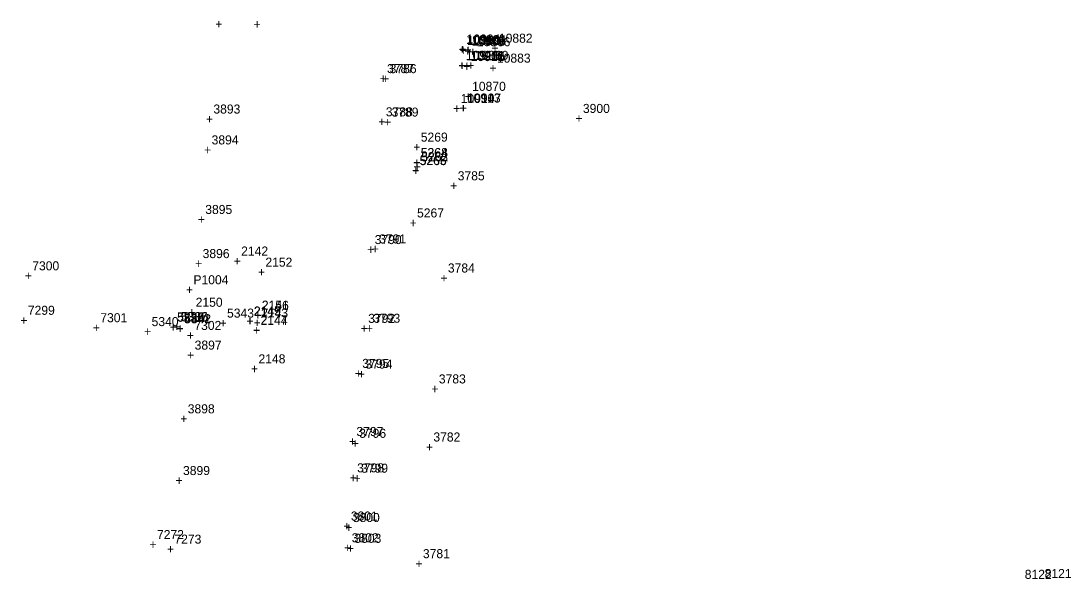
# Model space of a CAD drawing. Extents: x 1136220 to 1137808, y 528804 to 531215.
# Drawn here: x 1137338.4 to 1137628.2, y 530067.9 to 530222 of the extents above; entities that cross this region are included whole.
import ezdxf

# ---------------------------------------------------------------- set-up
doc = ezdxf.new("R2010")
doc.units = 0
for name, color, linetype in [('S_Buildings_SillElevation', 7, 'Continuous'), ('S_Curb_Type_1', 7, 'Continuous'), ('S_Drainage_CB', 7, 'Continuous'), ('S_Drainage_Culvert_Top', 7, 'Continuous'), ('S_Drainage_Invert', 7, 'Continuous'), ('S_Drainage_Sump', 7, 'Continuous'), ('S_Fencing_Gate', 7, 'Continuous'), ('S_Fencing_Picket', 7, 'Continuous'), ('S_Ground_Elevation', 7, 'Continuous'), ('S_Ground_SpotElevation', 7, 'Continuous'), ('S_Property_ConcPad', 7, 'Continuous'), ('S_Property_IronPipeFound', 7, 'Continuous'), ('S_Roadway_Drive_Gravel', 7, 'Continuous'), ('S_Roadway_Edge_Pavement', 7, 'Continuous'), ('S_Roadway_Sidewalks', 7, 'Continuous'), ('S_Utilities_UG_Sanitary_MH', 7, 'Continuous'), ('S_Utilities_UG_Water_Line', 7, 'Continuous')]:
    doc.layers.add(name, color=color, linetype=linetype)

msp = doc.modelspace()

# ---------------------------------------------------------------- texts
at = {"layer": 'S_Buildings_SillElevation'}
for s, p in [('+', (1137392.01, 530219.93)), ('3893', (1137391.47, 530196.46)), ('3900', (1137493.47, 530196.63)), ('+', (1137389.41, 530193.71)), ('+', (1137491.41, 530193.88)), ('3894', (1137390.98, 530187.94)), ('+', (1137388.92, 530185.19)), ('3785', (1137458.92, 530178.03)), ('+', (1137456.85, 530175.28)), ('3895', (1137389.23, 530168.73)), ('+', (1137387.17, 530165.98)), ('3896', (1137388.5, 530156.55)), ('+', (1137386.44, 530153.8)), ('3784', (1137456.2, 530152.57)), ('+', (1137454.14, 530149.82)), ('3897', (1137386.3, 530131.27)), ('+', (1137384.24, 530128.52)), ('3783', (1137453.71, 530121.94)), ('+', (1137451.65, 530119.19)), ('3898', (1137384.39, 530113.68)), ('+', (1137382.33, 530110.93)), ('3782', (1137452.2, 530105.9)), ('+', (1137450.14, 530103.15)), ('3899', (1137383.09, 530096.64)), ('+', (1137381.03, 530093.89)), ('3781', (1137449.31, 530073.68)), ('+', (1137447.25, 530070.93))]:
    msp.add_text(s, height=2.5, dxfattribs=at).set_placement(p)
at = {"layer": 'S_Curb_Type_1'}
for s, p in [('10909', (1137461.54, 530215.39)), ('10908', (1137462.78, 530215.19)), ('+', (1137459.48, 530212.64)), ('+', (1137460.72, 530212.44)), ('10910', (1137461.16, 530211.29)), ('10911', (1137462.57, 530211.28)), ('+', (1137459.09, 530208.54)), ('+', (1137460.51, 530208.53))]:
    msp.add_text(s, height=2.5, dxfattribs=at).set_placement(p)
at = {"layer": 'S_Drainage_CB'}
for s, p in [('+', (1137402.56, 530219.9)), ('5262', (1137448.87, 530183.26)), ('+', (1137446.81, 530180.51)), ('5336', (1137382.52, 530139.15)), ('+', (1137380.46, 530136.4))]:
    msp.add_text(s, height=2.5, dxfattribs=at).set_placement(p)
at = {"layer": 'S_Drainage_Culvert_Top'}
for s, p in [('5269', (1137448.72, 530188.71)), ('+', (1137446.66, 530185.96)), ('5268', (1137448.75, 530184.46)), ('5266', (1137448.45, 530182.22)), ('+', (1137446.39, 530179.47)), ('+', (1137446.69, 530181.71)), ('5267', (1137447.69, 530167.78)), ('+', (1137445.63, 530165.03)), ('2152', (1137405.83, 530154.18)), ('+', (1137403.77, 530151.43)), ('2150', (1137386.58, 530143.11)), ('2151', (1137404.84, 530142.31)), ('5339', (1137381.48, 530138.97)), ('5342', (1137383.39, 530138.53)), ('+', (1137384.52, 530140.36)), ('5343', (1137395.24, 530140.11)), ('2149', (1137402.69, 530140.65)), ('+', (1137402.78, 530139.56)), ('2147', (1137404.5, 530138.21)), ('5340', (1137374.42, 530137.77)), ('+', (1137379.42, 530136.22)), ('+', (1137381.33, 530135.78)), ('+', (1137393.18, 530137.36)), ('+', (1137400.63, 530137.9)), ('+', (1137372.36, 530135.02)), ('+', (1137402.44, 530135.46)), ('2148', (1137403.92, 530127.48)), ('+', (1137401.86, 530124.73))]:
    msp.add_text(s, height=2.5, dxfattribs=at).set_placement(p)
at = {"layer": 'S_Drainage_Invert'}
for s, p in [('5264', (1137448.68, 530184.43)), ('5265', (1137448.39, 530182.27)), ('+', (1137446.33, 530179.52)), ('+', (1137446.62, 530181.68)), ('2146', (1137404.86, 530142.27)), ('5338', (1137381.45, 530139.07)), ('5341', (1137383.38, 530138.62)), ('2145', (1137402.62, 530140.69)), ('+', (1137402.8, 530139.52)), ('2144', (1137404.5, 530138.12)), ('+', (1137379.39, 530136.32)), ('+', (1137381.32, 530135.87)), ('+', (1137400.56, 530137.94)), ('+', (1137402.44, 530135.37))]:
    msp.add_text(s, height=2.5, dxfattribs=at).set_placement(p)
at = {"layer": 'S_Drainage_Sump'}
for s, p in [('5263', (1137448.79, 530183.3)), ('+', (1137446.73, 530180.55)), ('5337', (1137382.42, 530139.09)), ('+', (1137380.36, 530136.34))]:
    msp.add_text(s, height=2.5, dxfattribs=at).set_placement(p)
at = {"layer": 'S_Fencing_Gate'}
for s, p in [('10906', (1137462.56, 530211.16)), ('+', (1137460.5, 530208.41))]:
    msp.add_text(s, height=2.5, dxfattribs=at).set_placement(p)
at = {"layer": 'S_Fencing_Picket'}
for s, p in [('10905', (1137462.86, 530215.59)), ('+', (1137460.8, 530212.84)), ('10907', (1137461.6, 530199.5)), ('+', (1137459.54, 530196.75))]:
    msp.add_text(s, height=2.5, dxfattribs=at).set_placement(p)
at = {"layer": 'S_Ground_Elevation'}
for s, p in [('10904', (1137461.39, 530215.82)), ('10903', (1137462.8, 530215.52)), ('+', (1137459.33, 530213.07)), ('+', (1137460.74, 530212.77)), ('10912', (1137462.51, 530210.96)), ('+', (1137460.45, 530208.21)), ('10913', (1137461.45, 530199.51)), ('+', (1137459.39, 530196.76)), ('8122', (1137615.44, 530067.97)), ('8121', (1137620.93, 530068.2))]:
    msp.add_text(s, height=2.5, dxfattribs=at).set_placement(p)
at = {"layer": 'S_Ground_SpotElevation'}
for s, p in [('10882', (1137470.28, 530216.03)), ('+', (1137468.22, 530213.28)), ('10883', (1137469.74, 530210.52)), ('+', (1137467.67, 530207.77))]:
    msp.add_text(s, height=2.5, dxfattribs=at).set_placement(p)
at = {"layer": 'S_Property_ConcPad'}
for s, p in [('10866', (1137464.16, 530215.05)), ('+', (1137462.1, 530212.3)), ('10869', (1137463.63, 530211.28)), ('+', (1137461.57, 530208.53)), ('10870', (1137462.89, 530202.74)), ('+', (1137460.83, 530199.99))]:
    msp.add_text(s, height=2.5, dxfattribs=at).set_placement(p)
at = {"layer": 'S_Property_IronPipeFound'}
for s, p in [('P1004', (1137385.96, 530149.32)), ('+', (1137383.9, 530146.57))]:
    msp.add_text(s, height=2.5, dxfattribs=at).set_placement(p)
at = {"layer": 'S_Roadway_Drive_Gravel'}
for s, p in [('7272', (1137375.9, 530078.96)), ('7273', (1137380.72, 530077.69)), ('+', (1137373.84, 530076.21)), ('+', (1137378.65, 530074.94))]:
    msp.add_text(s, height=2.5, dxfattribs=at).set_placement(p)
at = {"layer": 'S_Roadway_Edge_Pavement'}
for s, p in [('7300', (1137341.47, 530153.17)), ('+', (1137339.41, 530150.42)), ('7299', (1137340.26, 530140.89)), ('7301', (1137360.26, 530138.84)), ('+', (1137338.2, 530138.14)), ('+', (1137358.2, 530136.09)), ('7302', (1137386.22, 530136.7)), ('+', (1137384.16, 530133.95))]:
    msp.add_text(s, height=2.5, dxfattribs=at).set_placement(p)
at = {"layer": 'S_Roadway_Sidewalks'}
for s, p in [('10916', (1137461.23, 530215.67)), ('+', (1137459.17, 530212.92)), ('10915', (1137461.21, 530211.19)), ('+', (1137459.15, 530208.44)), ('10914', (1137459.74, 530199.37)), ('+', (1137457.68, 530196.62))]:
    msp.add_text(s, height=2.5, dxfattribs=at).set_placement(p)
at = {"layer": 'S_Utilities_UG_Sanitary_MH'}
for s, p in [('2142', (1137399.14, 530157.25)), ('+', (1137397.08, 530154.5)), ('2143', (1137404.66, 530140.19)), ('+', (1137402.59, 530137.44))]:
    msp.add_text(s, height=2.5, dxfattribs=at).set_placement(p)
at = {"layer": 'S_Utilities_UG_Water_Line'}
for s, p in [('3787', (1137439.41, 530207.64)), ('3786', (1137440.12, 530207.62)), ('+', (1137437.35, 530204.89)), ('+', (1137438.06, 530204.87)), ('3788', (1137439.07, 530195.7)), ('3789', (1137440.65, 530195.62)), ('+', (1137437, 530192.95)), ('+', (1137438.59, 530192.87)), ('3790', (1137436, 530160.42)), ('3791', (1137437.23, 530160.6)), ('+', (1137433.94, 530157.67)), ('+', (1137435.17, 530157.85)), ('3792', (1137434.19, 530138.65)), ('3793', (1137435.6, 530138.7)), ('+', (1137432.13, 530135.9)), ('+', (1137433.54, 530135.95)), ('3795', (1137432.56, 530126.22)), ('3794', (1137433.44, 530126.03)), ('+', (1137430.5, 530123.47)), ('+', (1137431.38, 530123.28)), ('3797', (1137430.95, 530107.42)), ('3796', (1137431.72, 530106.92)), ('+', (1137428.89, 530104.67)), ('+', (1137429.66, 530104.17)), ('3798', (1137431.16, 530097.38)), ('3799', (1137432.25, 530097.28)), ('+', (1137429.1, 530094.63)), ('+', (1137430.19, 530094.53)), ('3801', (1137429.4, 530084.07)), ('3800', (1137429.96, 530083.66)), ('+', (1137427.34, 530081.32)), ('+', (1137427.9, 530080.91)), ('3802', (1137429.64, 530078.07)), ('3803', (1137430.39, 530077.92)), ('+', (1137427.58, 530075.32)), ('+', (1137428.33, 530075.17))]:
    msp.add_text(s, height=2.5, dxfattribs=at).set_placement(p)

doc.saveas('drawing.dxf')
